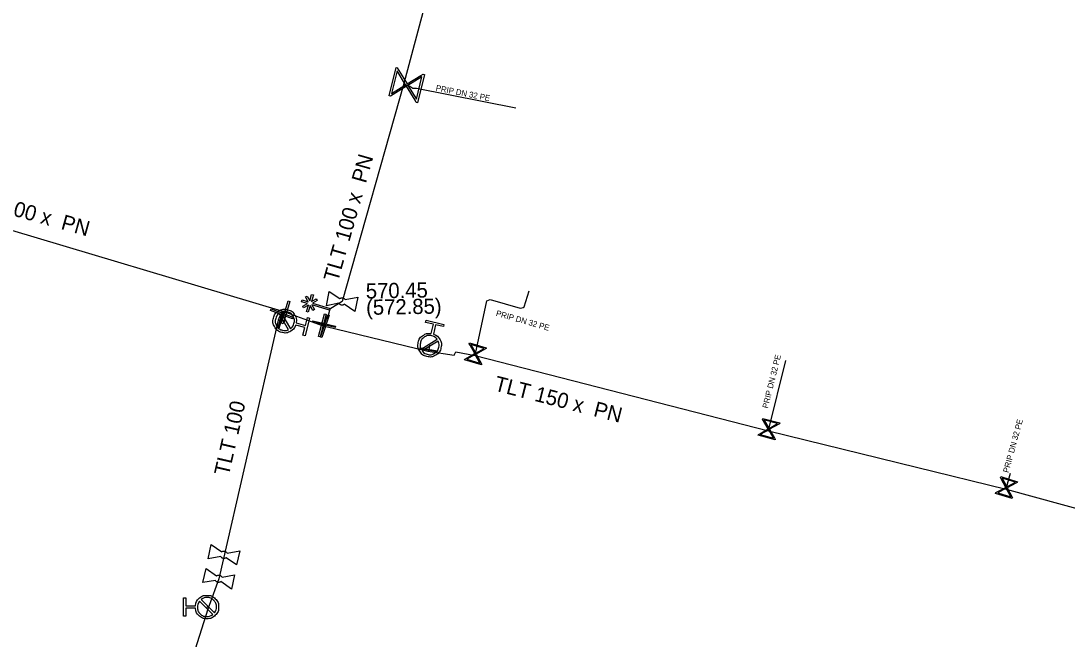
# Model space of a CAD drawing. Extents: x -643842 to -636370, y -1119190 to -1110210.
# Drawn here: x -641943.4 to -641853.7, y -1115125 to -1115072.1 of the extents above; entities that cross this region are included whole.
import ezdxf

# ---------------------------------------------------------------- set-up
doc = ezdxf.new("R2010")
doc.units = 0
for name, color, linetype in [('2', 7, 'Continuous'), ('22', 7, 'Continuous'), ('Default', 7, 'Continuous'), ('Level 16', 7, 'Continuous'), ('Level 20', 7, 'Continuous'), ('Level 21', 7, 'Continuous'), ('Level 23', 7, 'Continuous'), ('Level 27', 7, 'Continuous'), ('Level 28', 7, 'Continuous'), ('Level 33', 7, 'Continuous')]:
    doc.layers.add(name, color=color, linetype=linetype)

msp = doc.modelspace()

# ---------------------------------------------------------------- linework, layer by layer
at = {"layer": '2'}
msp.add_lwpolyline([(-641918.799, -1115096.289), (-641919.316, -1115096.134), (-641919.271, -1115095.984), (-641918.759, -1115096.138), (-641918.982, -1115095.725), (-641918.844, -1115095.652), (-641918.623, -1115096.061), (-641918.457, -1115095.51), (-641918.307, -1115095.554), (-641918.476, -1115096.116), (-641918.059, -1115095.89), (-641917.985, -1115096.027), (-641918.393, -1115096.248), (-641916.877, -1115096.703), (-641916.922, -1115096.852), (-641918.443, -1115096.396), (-641918.218, -1115096.811), (-641918.356, -1115096.884), (-641918.582, -1115096.468), (-641918.75, -1115097.028), (-641918.899, -1115096.983), (-641918.734, -1115096.432), (-641919.143, -1115096.651), (-641919.216, -1115096.514), (-641918.799, -1115096.289)], dxfattribs=at)
at = {"layer": 'Default'}
for points in [[(-641916.045, -1115095.864), (-641916.004, -1115095.832), (-641915.954, -1115095.814), (-641915.872, -1115095.788), (-641915.791, -1115095.803), (-641915.711, -1115095.818), (-641915.647, -1115095.873), (-641915.605, -1115095.908), (-641915.579, -1115095.954)], [(-641919.82, -1115098.133), (-641919.94, -1115098.473), (-641920.257, -1115098.656), (-641920.614, -1115098.863), (-641921.016, -1115098.757), (-641921.417, -1115098.652), (-641921.625, -1115098.294), (-641921.832, -1115097.936), (-641921.727, -1115097.534), (-641921.622, -1115097.135), (-641921.265, -1115096.926), (-641920.908, -1115096.717), (-641920.507, -1115096.823), (-641920.105, -1115096.929), (-641919.896, -1115097.285), (-641919.708, -1115097.6), (-641919.773, -1115097.955)], [(-641915.656, -1115096.355), (-641915.697, -1115096.388), (-641915.749, -1115096.405), (-641915.828, -1115096.432), (-641915.909, -1115096.417), (-641915.989, -1115096.402), (-641916.055, -1115096.345), (-641916.096, -1115096.312), (-641916.122, -1115096.266)], [(-641921.247, -1115097.137), (-641921.47, -1115097.303), (-641921.543, -1115097.582), (-641921.629, -1115097.907), (-641921.46, -1115098.198), (-641921.291, -1115098.489), (-641920.964, -1115098.575), (-641920.685, -1115098.648), (-641920.431, -1115098.535)], [(-641920.273, -1115098.443), (-641920.046, -1115098.279), (-641919.972, -1115097.996), (-641919.886, -1115097.669), (-641920.055, -1115097.379), (-641920.224, -1115097.089), (-641920.551, -1115097.003), (-641920.834, -1115096.929), (-641921.089, -1115097.045)], [(-641908.02, -1115098.902), (-641907.677, -1115099.013), (-641907.486, -1115099.326), (-641907.271, -1115099.678), (-641907.367, -1115100.083), (-641907.462, -1115100.486), (-641907.815, -1115100.702), (-641908.167, -1115100.918), (-641908.572, -1115100.822), (-641908.973, -1115100.727), (-641909.191, -1115100.376), (-641909.408, -1115100.024), (-641909.313, -1115099.621), (-641909.217, -1115099.216), (-641908.866, -1115098.998), (-641908.554, -1115098.803), (-641908.198, -1115098.86)], [(-641907.698, -1115099.348), (-641907.868, -1115099.125), (-641908.153, -1115099.057), (-641908.482, -1115098.979), (-641908.767, -1115099.155), (-641909.053, -1115099.331), (-641909.131, -1115099.66), (-641909.199, -1115099.945), (-641909.076, -1115100.197)], [(-641908.98, -1115100.352), (-641908.809, -1115100.571), (-641908.528, -1115100.638), (-641908.201, -1115100.716), (-641907.915, -1115100.54), (-641907.628, -1115100.364), (-641907.55, -1115100.035), (-641907.483, -1115099.754), (-641907.602, -1115099.503)], [(-641925.791, -1115118.069), (-641925.833, -1115118.101), (-641925.885, -1115118.117), (-641925.965, -1115118.142), (-641926.045, -1115118.125), (-641926.125, -1115118.108), (-641926.19, -1115118.05), (-641926.23, -1115118.015), (-641926.255, -1115117.969)], [(-641926.17, -1115117.569), (-641926.128, -1115117.538), (-641926.077, -1115117.522), (-641925.994, -1115117.497), (-641925.914, -1115117.514), (-641925.834, -1115117.531), (-641925.771, -1115117.587), (-641925.73, -1115117.623), (-641925.706, -1115117.67)], [(-641926.235, -1115120.121), (-641926.277, -1115120.153), (-641926.33, -1115120.168), (-641926.41, -1115120.192), (-641926.49, -1115120.174), (-641926.57, -1115120.156), (-641926.634, -1115120.097), (-641926.673, -1115120.062), (-641926.698, -1115120.015)], [(-641926.606, -1115119.616), (-641926.564, -1115119.586), (-641926.513, -1115119.57), (-641926.43, -1115119.547), (-641926.35, -1115119.565), (-641926.27, -1115119.583), (-641926.208, -1115119.64), (-641926.168, -1115119.677), (-641926.143, -1115119.724)], [(-641928.427, -1115122.203), (-641928.398, -1115121.844), (-641928.138, -1115121.586), (-641927.845, -1115121.295), (-641927.429, -1115121.295), (-641927.015, -1115121.295), (-641926.723, -1115121.588), (-641926.431, -1115121.881), (-641926.431, -1115122.297), (-641926.431, -1115122.709), (-641926.723, -1115123.002), (-641927.015, -1115123.295), (-641927.429, -1115123.295), (-641927.845, -1115123.295), (-641928.138, -1115123.004), (-641928.4, -1115122.746), (-641928.427, -1115122.387)], [(-641928.068, -1115121.787), (-641928.245, -1115122.004), (-641928.245, -1115122.297), (-641928.245, -1115122.635), (-641928.008, -1115122.872), (-641927.771, -1115123.109), (-641927.433, -1115123.109), (-641927.14, -1115123.109), (-641926.923, -1115122.932)], [(-641926.794, -1115122.803), (-641926.62, -1115122.586), (-641926.62, -1115122.297), (-641926.62, -1115121.961), (-641926.858, -1115121.723), (-641927.095, -1115121.484), (-641927.433, -1115121.484), (-641927.722, -1115121.484), (-641927.939, -1115121.658)]]:
    msp.add_open_spline(points, degree=3, dxfattribs=at)
at = {"layer": 'Level 16'}
for points in [[(-641908.791, -1115076.649), (-641909.379, -1115079.079), (-641909.485, -1115079.053), (-641909.591, -1115078.867), (-641910.322, -1115077.673), (-641911.702, -1115078.517), (-641911.809, -1115078.491), (-641911.221, -1115076.061), (-641911.115, -1115076.087), (-641910.274, -1115077.471), (-641909.08, -1115076.74), (-641908.898, -1115076.623), (-641908.791, -1115076.649)], [(-641911.597, -1115078.281), (-641910.399, -1115077.547), (-641911.131, -1115076.352), (-641911.597, -1115078.281)], [(-641909.005, -1115076.867), (-641910.197, -1115077.596), (-641909.469, -1115078.786), (-641909.005, -1115076.867)], [(-641921.927, -1115096.755), (-641920.058, -1115097.469), (-641920.103, -1115097.586), (-641921.971, -1115096.872), (-641921.927, -1115096.755)], [(-641920.34, -1115096.1), (-641920.911, -1115098.016), (-641921.03, -1115097.981), (-641920.46, -1115096.064), (-641920.34, -1115096.1)], [(-641921.363, -1115098.405), (-641920.931, -1115096.968), (-641920.841, -1115096.995), (-641921.273, -1115098.432), (-641921.363, -1115098.405)], [(-641917.22, -1115097.211), (-641917.739, -1115099.142), (-641917.86, -1115099.11), (-641917.34, -1115097.178), (-641917.22, -1115097.211)], [(-641916.95, -1115097.299), (-641917.572, -1115099.199), (-641917.691, -1115099.161), (-641917.068, -1115097.26), (-641916.95, -1115097.299)], [(-641916.438, -1115098.341), (-641918.389, -1115097.899), (-641918.361, -1115097.777), (-641916.41, -1115098.219), (-641916.438, -1115098.341)], [(-641909.141, -1115100.075), (-641907.663, -1115100.333), (-641907.68, -1115100.426), (-641909.157, -1115100.167), (-641909.141, -1115100.075)], [(-641904.918, -1115099.669), (-641903.478, -1115100.091), (-641903.497, -1115100.154), (-641903.612, -1115100.212), (-641904.348, -1115100.616), (-641903.882, -1115101.467), (-641903.901, -1115101.53), (-641905.34, -1115101.108), (-641905.321, -1115101.045), (-641904.468, -1115100.581), (-641904.872, -1115099.844), (-641904.936, -1115099.732), (-641904.918, -1115099.669)], [(-641904.793, -1115099.803), (-641904.391, -1115100.539), (-641903.657, -1115100.136), (-641904.793, -1115099.803)], [(-641904.02, -1115101.397), (-641904.426, -1115100.658), (-641905.163, -1115101.062), (-641904.02, -1115101.397)], [(-641878.717, -1115107.969), (-641880.164, -1115107.572), (-641880.146, -1115107.509), (-641880.032, -1115107.449), (-641879.303, -1115107.032), (-641879.784, -1115106.189), (-641879.767, -1115106.126), (-641878.32, -1115106.522), (-641878.338, -1115106.586), (-641879.183, -1115107.065), (-641878.766, -1115107.794), (-641878.699, -1115107.905), (-641878.717, -1115107.969)], [(-641879.645, -1115106.256), (-641879.227, -1115106.988), (-641878.496, -1115106.571), (-641879.645, -1115106.256)], [(-641878.844, -1115107.837), (-641879.259, -1115107.108), (-641879.986, -1115107.524), (-641878.844, -1115107.837)], [(-641859.366, -1115111.123), (-641857.932, -1115111.564), (-641857.952, -1115111.627), (-641858.067, -1115111.683), (-641858.809, -1115112.077), (-641858.354, -1115112.935), (-641858.373, -1115112.998), (-641859.807, -1115112.556), (-641859.788, -1115112.493), (-641858.928, -1115112.041), (-641859.322, -1115111.299), (-641859.385, -1115111.186), (-641859.366, -1115111.123)], [(-641859.243, -1115111.259), (-641858.85, -1115112), (-641858.111, -1115111.607), (-641859.243, -1115111.259)], [(-641858.491, -1115112.863), (-641858.887, -1115112.119), (-641859.63, -1115112.513), (-641858.491, -1115112.863)]]:
    msp.add_lwpolyline(points, dxfattribs=at)
at = {"layer": 'Level 21'}
for points in [[(-641876.51, -1114951.69), (-641876.59, -1114951.98), (-641878.19, -1114957.945), (-641879.79, -1114963.91), (-641881.42, -1114969.86), (-641885.21, -1114983.94), (-641886.41, -1114988.51), (-641891.51, -1115006.94), (-641891.63, -1115007.37), (-641894.1, -1115016.92), (-641894.94, -1115020.08), (-641896.75, -1115026.7), (-641899.96, -1115038.29), (-641901.11, -1115042.49), (-641903.45, -1115050.96), (-641903.53, -1115051.29), (-641905.22, -1115057.45), (-641910.55, -1115077.42), (-641915.85, -1115096.11), (-641916.9, -1115096.78)], [(-642007.07, -1115072.95), (-641998.27, -1115075.93), (-641981.25, -1115080.04), (-641969.77, -1115082.85), (-641967.989, -1115083.295), (-641961.6, -1115084.89), (-641959.404, -1115085.515), (-641956.89, -1115086.23), (-641946.695, -1115089.266), (-641921.03, -1115096.91), (-641920.865, -1115096.976), (-641920.685, -1115097.04), (-641917.54, -1115098.16), (-641917.439, -1115098.191)], [(-641916.9, -1115096.78), (-641917.045, -1115097.325), (-641917.4, -1115098.06), (-641917.439, -1115098.191)], [(-641920.865, -1115096.976), (-641921.015, -1115097.17), (-641921.24, -1115097.48), (-641921.32, -1115097.7), (-641926.42, -1115119.87), (-641927.25, -1115122.17), (-641927.294, -1115122.295), (-641927.36, -1115122.48), (-641928.81, -1115127.08), (-641930.27, -1115132.24), (-641935.79, -1115139.4), (-641939.75, -1115144.21), (-641945.57, -1115147.83), (-641949.11, -1115149.87), (-641954.17, -1115150.87), (-641967.14, -1115152.81), (-641969.37, -1115156.26), (-641972.84, -1115156.79), (-641973.05, -1115156.8), (-641973.35, -1115156.9), (-641973.55, -1115156.85)], [(-641917.439, -1115098.191), (-641917.32, -1115098.23), (-641908.5, -1115100.37), (-641906.24, -1115100.72), (-641906.09, -1115100.42), (-641904.439, -1115100.732), (-641879.27, -1115107.19), (-641866.578, -1115110.307), (-641858.91, -1115112.19), (-641825.6, -1115121.31), (-641822.41, -1115121.84)]]:
    msp.add_lwpolyline(points, dxfattribs=at)
at = {"layer": 'Level 23'}
for points in [[(-641910.55, -1115077.42), (-641910.3, -1115077.57), (-641910.04, -1115077.66), (-641909.78, -1115077.82), (-641909.47, -1115077.84), (-641900.938, -1115079.518)], [(-641904.439, -1115100.732), (-641904.41, -1115100.6), (-641903.421, -1115096.069), (-641903.138, -1115095.94), (-641900.57, -1115096.671), (-641900.434, -1115096.665), (-641900.328, -1115096.635), (-641900.234, -1115096.582), (-641899.813, -1115095.186)], [(-641921.32, -1115097.7), (-641921.102, -1115097.7), (-641920.76, -1115097.79)], [(-641908.34, -1115099.85), (-641908.41, -1115100.25), (-641908.5, -1115100.37)], [(-641879.27, -1115107.19), (-641879.242, -1115107.048), (-641877.792, -1115101.173)], [(-641858.91, -1115112.19), (-641858.87, -1115112.06), (-641858.531, -1115110.815)], [(-641927.294, -1115122.295), (-641927.431, -1115122.295)]]:
    msp.add_lwpolyline(points, dxfattribs=at)
at = {"layer": 'Level 28'}
for points in [[(-641917.195, -1115096.489), (-641916.961, -1115095.262), (-641916.045, -1115095.864)], [(-641915.579, -1115095.954), (-641914.505, -1115095.731), (-641914.739, -1115096.958), (-641915.656, -1115096.355)], [(-641916.122, -1115096.266), (-641917.195, -1115096.489)], [(-641927.333, -1115118.168), (-641927.071, -1115116.946), (-641926.17, -1115117.569)], [(-641926.255, -1115117.969), (-641927.333, -1115118.168)], [(-641925.706, -1115117.67), (-641924.627, -1115117.471), (-641924.889, -1115118.693), (-641925.791, -1115118.069)], [(-641927.778, -1115120.198), (-641927.498, -1115118.98), (-641926.606, -1115119.616)], [(-641926.698, -1115120.015), (-641927.778, -1115120.198)], [(-641926.143, -1115119.724), (-641925.062, -1115119.541), (-641925.342, -1115120.759), (-641926.235, -1115120.121)]]:
    msp.add_lwpolyline(points, dxfattribs=at)
at = {"layer": 'Level 33'}
for points in [[(-641920.431, -1115098.535), (-641921.247, -1115097.137)], [(-641921.089, -1115097.045), (-641920.273, -1115098.443)], [(-641919.773, -1115097.955), (-641918.98, -1115098.164), (-641918.805, -1115097.497), (-641918.627, -1115097.544), (-641919.025, -1115099.055), (-641919.202, -1115099.008), (-641919.027, -1115098.341), (-641919.82, -1115098.133)], [(-641908.198, -1115098.86), (-641908.009, -1115098.061), (-641908.68, -1115097.902), (-641908.637, -1115097.724), (-641907.117, -1115098.084), (-641907.16, -1115098.263), (-641907.83, -1115098.104), (-641908.02, -1115098.902)], [(-641909.076, -1115100.197), (-641907.698, -1115099.348)], [(-641907.602, -1115099.503), (-641908.98, -1115100.352)], [(-641928.427, -1115122.387), (-641929.247, -1115122.387), (-641929.247, -1115123.076), (-641929.431, -1115123.076), (-641929.431, -1115121.514), (-641929.247, -1115121.514), (-641929.247, -1115122.203), (-641928.427, -1115122.203)], [(-641926.923, -1115122.932), (-641928.068, -1115121.787)], [(-641927.939, -1115121.658), (-641926.794, -1115122.803)]]:
    msp.add_lwpolyline(points, dxfattribs=at)

# ---------------------------------------------------------------- texts
at = {"layer": '22'}
for rotation, p in [(348.87357, (-641907.842, -1115078.04)), (344.1106, (-641902.689, -1115097.335)), (76.13601, (-641879.336, -1115105.31)), (74.76824, (-641858.699, -1115110.83))]:
    msp.add_text('PRIP DN 32 PE', height=0.5, rotation=rotation, dxfattribs=at).set_placement(p)
at = {"layer": 'Level 20'}
for s, rotation, p in [('TLT 100 x  PN ', 74.16804, (-641916.209, -1115094.499)), ('TLT 100 x  PN ', 344.37491, (-641948.492, -1115087.522)), ('TLT 150 x  PN ', 345.60917, (-641902.878, -1115103.729)), ('TLT 100', 77.045, (-641925.567, -1115111.111))]:
    msp.add_text(s, height=1.3, rotation=rotation, dxfattribs=at).set_placement(p)
at = {"layer": 'Level 27'}
for s, p in [('570.45', (-641913.802, -1115095.862)), ('(572.85)', (-641913.777, -1115097.262))]:
    msp.add_text(s, height=1.3, rotation=1, dxfattribs=at).set_placement(p)

doc.saveas('drawing.dxf')
